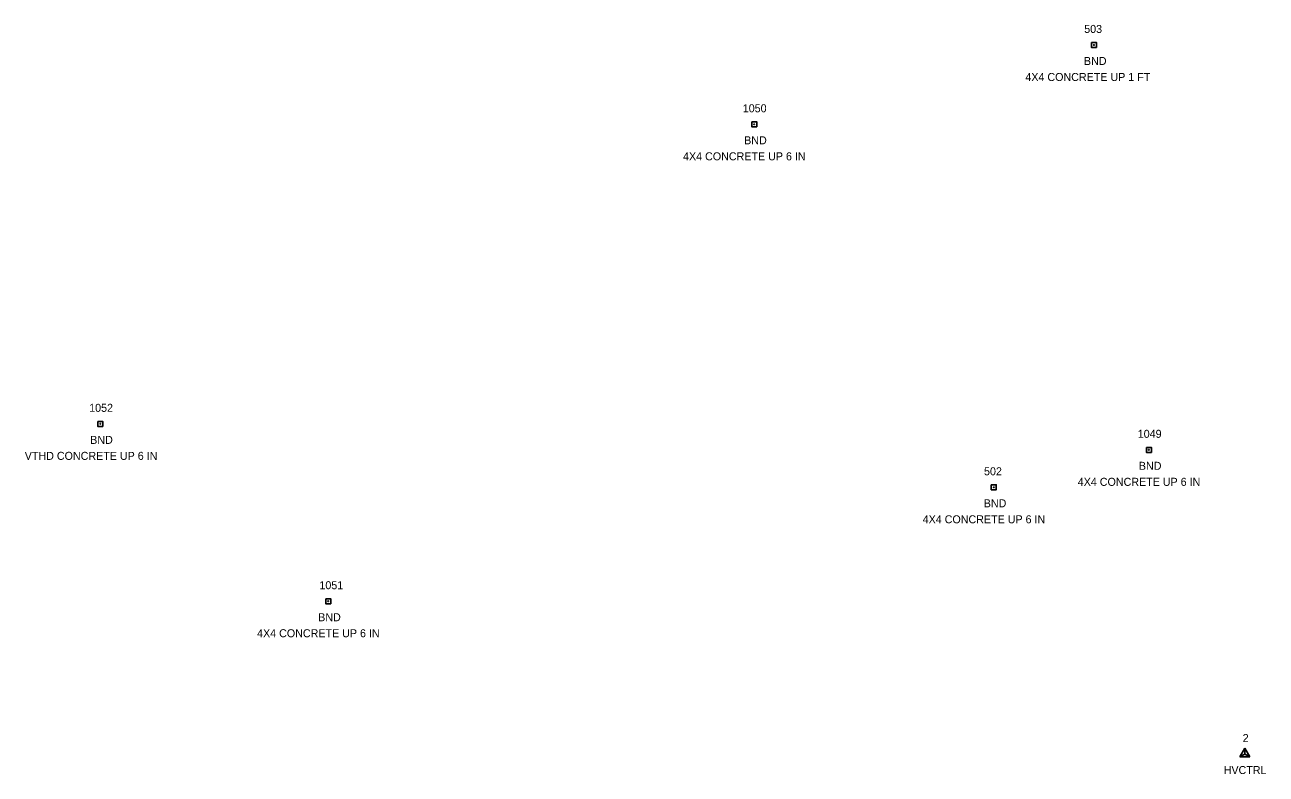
# Model space of a CAD drawing. Extents: x 1764889 to 1767296, y 695936 to 698960.
# Drawn here: x 1765783.6 to 1766093.7, y 696734 to 696921.2 of the extents above; entities that cross this region are included whole.
import ezdxf

# ---------------------------------------------------------------- set-up
doc = ezdxf.new("R2010")
doc.units = 0
for name, color, linetype in [('C_A', 7, 'Continuous'), ('C_I', 7, 'Continuous'), ('CPSM', 7, 'Continuous'), ('Level 18', 7, 'Continuous'), ('M_A', 7, 'Continuous'), ('M_C', 7, 'Continuous'), ('M_I', 7, 'Continuous')]:
    doc.layers.add(name, color=color, linetype=linetype)

msp = doc.modelspace()

# ---------------------------------------------------------------- linework, layer by layer
at = {"layer": 'CPSM'}
for p, q in [((1766087.18, 696738.32), (1766088.43, 696740.48)), ((1766087.18, 696738.32), (1766088.43, 696740.48)), ((1766089.68, 696738.32), (1766088.43, 696740.48)), ((1766088.43, 696739.04), (1766088.43, 696740.48)), ((1766089.68, 696738.32), (1766088.43, 696740.48)), ((1766088.43, 696739.04), (1766088.43, 696740.48)), ((1766087.18, 696738.32), (1766088.43, 696739.04)), ((1766087.18, 696738.32), (1766088.43, 696739.04)), ((1766087.18, 696738.32), (1766089.68, 696738.32)), ((1766087.18, 696738.32), (1766089.68, 696738.32)), ((1766088.43, 696739.04), (1766088.43, 696739.04)), ((1766088.43, 696739.04), (1766089.68, 696738.32)), ((1766088.43, 696739.04), (1766088.43, 696739.04)), ((1766088.43, 696739.04), (1766089.68, 696738.32))]:
    msp.add_line(p, q, dxfattribs=at)
at = {"layer": 'Level 18'}
for points in [[(1766050.08, 696916.83), (1766051.33, 696916.83), (1766051.33, 696915.58), (1766050.08, 696915.58)], [(1765965.19, 696897), (1765966.44, 696897), (1765966.44, 696895.75), (1765965.19, 696895.75)], [(1765801.8, 696822.16), (1765803.05, 696822.16), (1765803.05, 696820.91), (1765801.8, 696820.91)], [(1766063.81, 696815.67), (1766065.06, 696815.67), (1766065.06, 696814.42), (1766063.81, 696814.42)], [(1766025.06, 696806.31), (1766026.31, 696806.31), (1766026.31, 696805.06), (1766025.06, 696805.06)], [(1765858.76, 696777.84), (1765860.01, 696777.84), (1765860.01, 696776.59), (1765858.76, 696776.59)]]:
    msp.add_lwpolyline(points, close=True, dxfattribs=at)
for centre in [(1766050.71, 696916.2), (1765965.82, 696896.38), (1765802.42, 696821.54), (1766064.43, 696815.05), (1766025.69, 696805.69), (1765859.38, 696777.22)]:
    msp.add_circle(centre, 0.0833, dxfattribs=at)

# ---------------------------------------------------------------- texts
at = {"layer": 'C_A'}
msp.add_text('HVCTRL', height=2, dxfattribs=at).set_placement((1766083.12, 696734.04))
msp.add_text('HVCTRL', height=2, dxfattribs=at).set_placement((1766083.12, 696734.04))
at = {"layer": 'C_I'}
msp.add_text('2', height=2, dxfattribs=at).set_placement((1766087.86, 696742.04))
msp.add_text('2', height=2, dxfattribs=at).set_placement((1766087.86, 696742.04))
at = {"layer": 'M_A'}
for p in [(1766048.2, 696911.2), (1765963.3, 696891.38), (1765799.91, 696816.54), (1766061.92, 696810.05), (1766023.17, 696800.69), (1765856.87, 696772.22)]:
    msp.add_text('BND', height=2, dxfattribs=at).set_placement(p)
at = {"layer": 'M_C'}
for s, p in [('4X4 CONCRETE UP 1 FT', (1766033.57, 696907.2)), ('4X4 CONCRETE UP 6 IN', (1765948.04, 696887.38)), ('VTHD CONCRETE UP 6 IN', (1765783.56, 696812.54)), ('4X4 CONCRETE UP 6 IN', (1766046.66, 696806.05)), ('4X4 CONCRETE UP 6 IN', (1766007.91, 696796.69)), ('4X4 CONCRETE UP 6 IN', (1765841.61, 696768.22))]:
    msp.add_text(s, height=2, dxfattribs=at).set_placement(p)
at = {"layer": 'M_I'}
for s, p in [('503', (1766048.27, 696919.2)), ('1050', (1765962.96, 696899.38)), ('1052', (1765799.65, 696824.54)), ('1049', (1766061.65, 696818.05)), ('502', (1766023.24, 696808.69)), ('1051', (1765857.18, 696780.22))]:
    msp.add_text(s, height=2, dxfattribs=at).set_placement(p)

doc.saveas('drawing.dxf')
